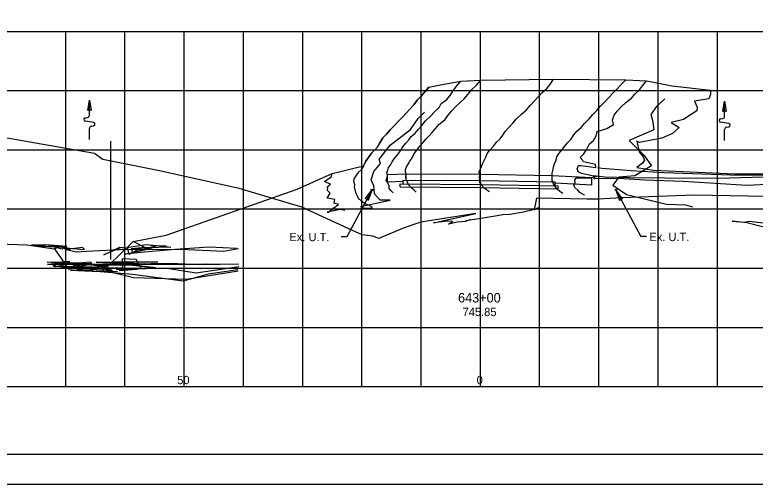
# Model space of a CAD drawing. Extents: x -46 to 154, y -27 to 78.
# Drawn here: x 104.44 to 116.94, y 55.68 to 63.61 of the extents above; entities that cross this region are included whole.
import ezdxf

# ---------------------------------------------------------------- set-up
doc = ezdxf.new("R2010")
doc.units = 0
for name, color, linetype in [('BD_X_Building', 7, 'Continuous'), ('DT_P_Contour_Minor', 7, 'Continuous'), ('DT_X_Break_Line', 7, 'Continuous'), ('DT_X_Contour_Major', 7, 'Continuous'), ('DT_X_Island', 7, 'Continuous'), ('DT_X_Spot_Elev', 7, 'Continuous'), ('DT_X_Void', 7, 'Continuous'), ('GE_P_Alignment_100_Stations', 7, 'Continuous'), ('HY_X_Water_Edge', 7, 'Continuous'), ('PF_X_Ground_Line', 7, 'Continuous'), ('PV_X_COP', 7, 'Continuous'), ('PV_X_Driveway', 7, 'Continuous'), ('PV_X_EOP', 7, 'Continuous'), ('SV_X_Break_Lines', 7, 'Continuous'), ('SV_X_Terrain_Boundary', 7, 'Continuous'), ('SV_X_Toe_of_Slope', 7, 'Continuous'), ('XS_P_Finished_Grade', 7, 'Continuous'), ('XS_P_Pavt_Layers', 7, 'Continuous'), ('XS_P_Text_Info', 7, 'Continuous'), ('XS_X_Pavt', 7, 'Continuous')]:
    doc.layers.add(name, color=color, linetype=linetype)

msp = doc.modelspace()

# ---------------------------------------------------------------- linework, layer by layer
at = {"layer": 'BD_X_Building'}
for points in [[(114.051, 60.565), (114.057, 60.563), (113.981, 60.606), (113.946, 60.646), (113.895, 60.693), (113.878, 60.736), (113.902, 60.772), (113.898, 60.822), (113.926, 60.853), (114.171, 60.854), (114.24, 60.879), (114.168, 60.893), (114.007, 60.927), (113.955, 60.954), (113.937, 61.008), (113.959, 61.063), (113.995, 61.064), (114.253, 61.031), (114.245, 61.077), (114.042, 61.126), (114.031, 61.149), (113.986, 61.197), (114.047, 61.259), (114.095, 61.324), (114.117, 61.371), (114.146, 61.429), (114.212, 61.484), (114.259, 61.565), (114.272, 61.634), (114.439, 61.689), (114.55, 61.755), (114.532, 61.831), (114.56, 61.913), (114.612, 61.98), (114.681, 62.055), (114.756, 62.129), (114.853, 62.201), (114.914, 62.274), (114.987, 62.343), (115.038, 62.407), (115.107, 62.495)], [(110.828, 60.599), (110.83, 60.6), (110.798, 60.636), (110.76, 60.671), (110.76, 60.721), (110.739, 60.77), (110.709, 60.813), (110.729, 60.862), (110.734, 60.902), (110.725, 60.942), (110.737, 60.984), (110.751, 61.027), (110.783, 61.069), (110.815, 61.123), (110.846, 61.177), (110.902, 61.24), (110.952, 61.308), (110.994, 61.378), (111.045, 61.439), (111.096, 61.498), (111.136, 61.552), (111.2, 61.609), (111.253, 61.669), (111.314, 61.737), (111.378, 61.815), (111.459, 61.894), (111.53, 61.968), (111.606, 62.041), (111.638, 62.108), (111.727, 62.172), (111.79, 62.247), (111.837, 62.32), (111.898, 62.4), (111.971, 62.489)]]:
    msp.add_lwpolyline(points, dxfattribs=at)
at = {"layer": 'DT_P_Contour_Minor'}
for p, q in [((105.673, 61.992), (105.702, 62.165)), ((105.702, 62.165), (105.731, 61.991)), ((105.702, 61.909), (105.702, 62.165)), ((116.394, 61.975), (116.423, 62.148)), ((116.423, 62.148), (116.452, 61.974)), ((116.423, 61.892), (116.423, 62.148)), ((105.632, 61.864), (105.672, 61.872)), ((105.673, 61.992), (105.673, 61.992)), ((105.731, 61.991), (105.731, 61.991)), ((116.394, 61.975), (116.394, 61.975)), ((116.452, 61.974), (116.452, 61.975)), ((105.772, 61.788), (105.633, 61.809)), ((116.353, 61.848), (116.393, 61.855)), ((116.493, 61.771), (116.354, 61.792)), ((105.702, 61.503), (105.702, 61.688)), ((105.733, 61.725), (105.773, 61.732)), ((116.423, 61.486), (116.423, 61.671)), ((116.454, 61.708), (116.494, 61.716)), ((110.469, 60.648), (110.047, 59.858)), ((110.355, 60.499), (110.469, 60.648)), ((110.469, 60.648), (110.409, 60.47)), ((114.703, 60.501), (114.59, 60.65)), ((114.59, 60.65), (114.649, 60.471)), ((114.59, 60.65), (115.011, 59.86)), ((110.355, 60.499), (110.355, 60.499)), ((114.703, 60.501), (114.703, 60.501)), ((110.409, 60.47), (110.409, 60.47)), ((114.649, 60.471), (114.649, 60.471)), ((110.047, 59.858), (109.952, 59.858)), ((115.106, 59.86), (115.011, 59.86))]:
    msp.add_line(p, q, dxfattribs=at)
for centre, radius, start, end in [((105.702, 61.947), 0.0527, 56.178, 122.8588), ((105.665, 61.909), 0.0375, 280.6197, 360), ((116.386, 61.892), 0.0375, 280.6197, 360), ((116.423, 61.931), 0.0527, 56.178, 122.8588), ((105.637, 61.837), 0.0281, 100.6197, 261.4692), ((105.768, 61.76), 0.0281, 280.6197, 81.4692), ((116.358, 61.82), 0.0281, 100.6197, 261.4692), ((116.489, 61.743), 0.0281, 280.6197, 81.4692), ((105.74, 61.688), 0.0375, 100.6197, 180), ((116.461, 61.671), 0.0375, 100.6197, 180), ((110.36, 60.443), 0.0563, 28.2924, 94.9732), ((114.699, 60.445), 0.0563, 85.0268, 151.7076)]:
    msp.add_arc(centre, radius, start, end, dxfattribs=at)
at = {"layer": 'DT_X_Break_Line'}
for p, q in [((98.302, 63.328), (126.302, 63.328)), ((105.302, 57.328), (105.302, 63.328)), ((106.302, 57.328), (106.302, 63.328)), ((107.302, 57.328), (107.302, 63.328)), ((108.302, 57.328), (108.302, 63.328)), ((109.302, 57.328), (109.302, 63.328)), ((110.302, 57.328), (110.302, 63.328)), ((111.302, 57.328), (111.302, 63.328)), ((112.302, 57.328), (112.302, 63.328)), ((113.302, 57.328), (113.302, 63.328)), ((114.302, 57.328), (114.302, 63.328)), ((115.302, 57.328), (115.302, 63.328)), ((116.302, 57.328), (116.302, 63.328)), ((98.302, 62.328), (126.302, 62.328)), ((98.302, 61.328), (126.302, 61.328)), ((98.302, 60.328), (126.302, 60.328)), ((98.302, 59.328), (126.302, 59.328)), ((98.302, 58.328), (126.302, 58.328)), ((98.302, 57.328), (126.302, 57.328))]:
    msp.add_line(p, q, dxfattribs=at)
at = {"layer": 'DT_X_Contour_Major'}
msp.add_lwpolyline([(95.552, 55.678), (129.552, 55.678), (129.552, 77.678), (95.552, 77.678)], close=True, dxfattribs=at)
at = {"layer": 'DT_X_Island'}
for p, q in [((110.732, 60.909), (111.048, 60.921)), ((110.732, 60.788), (110.732, 60.909)), ((111.048, 60.816), (111.048, 60.921)), ((111.048, 60.921), (112.302, 60.913)), ((112.302, 60.913), (113.513, 60.891)), ((113.513, 60.787), (113.513, 60.891)), ((113.513, 60.891), (114.182, 60.858)), ((110.732, 60.788), (110.998, 60.798)), ((110.948, 60.75), (112.301, 60.742)), ((110.948, 60.7), (110.948, 60.75)), ((110.998, 60.817), (112.301, 60.808)), ((110.998, 60.75), (110.998, 60.817)), ((112.3, 60.808), (113.563, 60.786)), ((113.563, 60.719), (113.563, 60.786)), ((113.563, 60.767), (114.182, 60.737)), ((114.182, 60.737), (114.182, 60.858)), ((110.948, 60.7), (112.3, 60.692)), ((112.298, 60.692), (113.613, 60.668)), ((112.299, 60.742), (113.613, 60.718)), ((113.613, 60.668), (113.613, 60.718))]:
    msp.add_line(p, q, dxfattribs=at)
at = {"layer": 'DT_X_Spot_Elev'}
msp.add_lwpolyline([(97.052, 77.178), (129.052, 77.178), (129.052, 56.178), (97.052, 56.178)], close=True, dxfattribs=at)
at = {"layer": 'GE_P_Alignment_100_Stations'}
msp.add_line((106.064, 59.472), (106.064, 61.472), dxfattribs=at)
at = {"layer": 'HY_X_Water_Edge'}
for points in [[(114.304, 61.048), (114.298, 61.041), (114.304, 61.024), (114.282, 61.024), (114.849, 60.978), (115.407, 60.944), (116.526, 60.904), (117.965, 60.9)], [(117.263, 60.872), (116.327, 60.843), (115.414, 60.849), (114.812, 60.851), (114.4, 60.866), (114.203, 60.886), (114.256, 60.873), (114.255, 60.87), (114.211, 60.858), (114.232, 60.844), (114.631, 60.848), (115.076, 60.822), (115.727, 60.797), (116.264, 60.763), (116.799, 60.728), (117.38, 60.756)]]:
    msp.add_lwpolyline(points, dxfattribs=at)
at = {"layer": 'PF_X_Ground_Line'}
for points in [[(108.208, 59.299), (107.708, 59.228), (107.287, 59.106), (106.429, 59.222), (105.818, 59.273), (105.48, 59.286), (105.548, 59.311), (105.584, 59.326), (105.567, 59.316), (105.433, 59.335), (105.63, 59.35), (105.741, 59.349), (105.762, 59.296), (105.714, 59.28), (105.15, 59.358), (105.094, 59.354), (105.424, 59.362), (105.484, 59.366), (105.653, 59.352), (105.694, 59.333), (105.572, 59.336), (105.259, 59.349), (105.132, 59.362), (105.065, 59.402), (105.13, 59.358), (105.301, 59.391), (105.528, 59.397), (105.479, 59.32), (105.346, 59.313)], [(108.225, 59.35), (107.505, 59.245), (107.016, 59.321), (106.302, 59.308), (106.156, 59.313), (106.381, 59.31), (106.408, 59.307), (106.37, 59.308), (106.203, 59.286), (106.499, 59.31), (106.578, 59.325), (106.49, 59.472), (106.257, 59.488), (106.259, 59.302), (106.328, 59.298), (106.243, 59.334), (106.231, 59.325), (105.985, 59.329), (105.871, 59.363), (105.73, 59.384), (105.866, 59.373), (106.054, 59.382), (106.383, 59.384), (106.825, 59.336), (106.396, 59.384), (106.335, 59.434), (106.024, 59.375)]]:
    msp.add_lwpolyline(points, dxfattribs=at)
at = {"layer": 'PV_X_COP'}
msp.add_lwpolyline([(111.43, 62.385), (111.357, 62.299), (111.303, 62.233), (111.232, 62.167), (111.178, 62.089), (111.111, 62.012), (111.049, 61.945), (110.979, 61.873), (110.912, 61.807), (110.849, 61.73), (110.782, 61.671), (110.719, 61.59), (110.653, 61.527), (110.606, 61.444), (110.558, 61.365), (110.518, 61.326), (110.461, 61.269), (110.414, 61.195), (110.368, 61.136), (110.327, 61.058), (110.291, 60.991), (110.236, 60.944), (110.2, 60.889), (110.17, 60.843), (110.162, 60.803), (110.166, 60.78), (110.179, 60.741), (110.173, 60.696), (110.182, 60.649), (110.199, 60.596), (110.223, 60.548), (110.244, 60.501), (110.281, 60.476), (110.322, 60.44), (110.365, 60.413), (110.414, 60.397), (110.461, 60.369), (110.468, 60.34), (110.279, 60.336)], dxfattribs=at)
at = {"layer": 'PV_X_Driveway'}
for points in [[(110.016, 60.302), (109.939, 60.318), (109.715, 60.272), (109.736, 60.275), (109.811, 60.338), (109.907, 60.404), (109.835, 60.427), (109.844, 60.486), (109.717, 60.512), (109.766, 60.596), (109.719, 60.638), (109.729, 60.682), (109.713, 60.7), (109.774, 60.748), (109.703, 60.773), (109.668, 60.792), (109.782, 60.872), (109.797, 60.928)], [(108.185, 59.659), (107.724, 59.681), (107.149, 59.644), (106.629, 59.599), (106.292, 59.565), (106.607, 59.63), (106.815, 59.69), (106.596, 59.65), (106.404, 59.661), (106.643, 59.685), (106.736, 59.676), (106.673, 59.646), (106.428, 59.585), (106.42, 59.656), (106.546, 59.639), (106.549, 59.652), (106.372, 59.561), (106.349, 59.661), (106.238, 59.675), (105.945, 59.554), (106.216, 59.684), (106.295, 59.67), (106.661, 59.728), (106.949, 59.697), (107.078, 59.683), (106.65, 59.671), (106.44, 59.777)], [(108.218, 59.656), (107.97, 59.607), (107.364, 59.639), (106.325, 59.641), (105.65, 59.609), (105.479, 59.599), (105.29, 59.642), (105.325, 59.662), (105.375, 59.635), (105.276, 59.668), (105.357, 59.665), (105.618, 59.645), (105.583, 59.677), (105.404, 59.652), (104.966, 59.723), (104.742, 59.708), (105.105, 59.686), (105.244, 59.656), (105.289, 59.693), (105.32, 59.691), (105.111, 59.713), (104.966, 59.72), (104.877, 59.706), (104.725, 59.719), (104.84, 59.72), (104.979, 59.702), (105.239, 59.68), (105.202, 59.686), (105.112, 59.656)]]:
    msp.add_lwpolyline(points, dxfattribs=at)
at = {"layer": 'PV_X_EOP'}
for points in [[(115.418, 62.188), (115.272, 62.059), (115.178, 61.924), (115.207, 61.826), (115.228, 61.663), (114.813, 61.484), (115.064, 61.232), (115.193, 61.056), (114.909, 60.888), (114.64, 60.865), (114.538, 60.728), (114.77, 60.572), (115.445, 60.411), (115.766, 60.4), (115.88, 60.366)], [(110.278, 60.37), (110.781, 60.475), (110.609, 60.478), (110.512, 60.582), (110.504, 60.719), (110.459, 60.82), (110.504, 60.96), (110.613, 61.095), (110.593, 61.167), (110.624, 61.203), (110.778, 61.406), (111.12, 61.669), (111.249, 61.857), (111.358, 61.961)]]:
    msp.add_lwpolyline(points, dxfattribs=at)
for centre in [(110.469, 60.648), (114.59, 60.65)]:
    msp.add_circle(centre, 0.0125, dxfattribs=at)
at = {"layer": 'SV_X_Break_Lines'}
for points in [[(111.217, 60.614), (111.215, 60.612), (111.177, 60.649), (111.133, 60.687), (111.091, 60.736), (111.071, 60.78), (111.051, 60.825), (111.046, 60.871), (111.05, 60.914), (111.039, 60.955), (111.04, 60.996), (111.054, 61.04), (111.081, 61.083), (111.109, 61.137), (111.149, 61.191), (111.177, 61.253), (111.229, 61.32), (111.279, 61.388), (111.336, 61.45), (111.383, 61.508), (111.436, 61.566), (111.488, 61.621), (111.542, 61.686), (111.601, 61.754), (111.699, 61.831), (111.754, 61.909), (111.819, 61.983), (111.889, 62.057), (111.962, 62.127), (112.026, 62.191), (112.095, 62.266), (112.154, 62.339), (112.234, 62.418), (112.308, 62.506)], [(113.691, 60.591), (113.641, 60.623), (113.598, 60.663), (113.563, 60.708), (113.537, 60.75), (113.519, 60.79), (113.511, 60.835), (113.513, 60.885), (113.511, 60.93), (113.522, 60.976), (113.538, 61.027), (113.55, 61.08), (113.579, 61.15), (113.595, 61.207), (113.632, 61.269), (113.682, 61.333), (113.722, 61.384), (113.771, 61.443), (113.826, 61.503), (113.881, 61.578), (113.929, 61.641), (114.002, 61.704), (114.059, 61.774), (114.137, 61.849), (114.202, 61.924), (114.267, 61.989), (114.33, 62.065), (114.404, 62.14), (114.468, 62.211), (114.535, 62.282), (114.606, 62.351), (114.665, 62.417), (114.756, 62.508)]]:
    msp.add_lwpolyline(points, dxfattribs=at)
at = {"layer": 'SV_X_Terrain_Boundary'}
msp.add_lwpolyline([(108.213, 59.279), (107.341, 59.136), (106.446, 59.166), (105.989, 59.277), (105.813, 59.278), (105.966, 59.273), (106.03, 59.322), (105.899, 59.337), (105.937, 59.289), (106.178, 59.273), (106.119, 59.267), (105.751, 59.272), (105.385, 59.291), (105.928, 59.319), (106.017, 59.328), (105.977, 59.313), (105.879, 59.323), (105.638, 59.343), (105.519, 59.352), (105.416, 59.394), (105.506, 59.352), (105.679, 59.389), (105.998, 59.353), (106.105, 59.27), (105.847, 59.34), (105.606, 59.335)], dxfattribs=at)
at = {"layer": 'SV_X_Toe_of_Slope'}
msp.add_lwpolyline([(112.454, 60.619), (112.445, 60.621), (112.406, 60.653), (112.349, 60.688), (112.332, 60.729), (112.293, 60.777), (112.295, 60.815), (112.286, 60.858), (112.293, 60.904), (112.28, 60.954), (112.304, 61.004), (112.323, 61.045), (112.337, 61.092), (112.364, 61.148), (112.393, 61.203), (112.416, 61.264), (112.461, 61.323), (112.521, 61.391), (112.572, 61.455), (112.636, 61.514), (112.682, 61.575), (112.722, 61.637), (112.786, 61.707), (112.851, 61.778), (112.913, 61.853), (112.996, 61.927), (113.083, 62), (113.146, 62.079), (113.217, 62.153), (113.278, 62.221), (113.344, 62.293), (113.422, 62.365), (113.472, 62.427), (113.538, 62.522)], dxfattribs=at)
at = {"layer": 'XS_P_Finished_Grade'}
for points in [[(108.211, 59.39), (107.688, 59.394), (107.261, 59.384), (106.43, 59.391), (105.798, 59.389), (105.433, 59.373), (105.458, 59.391), (105.554, 59.397), (105.556, 59.392), (105.422, 59.395), (105.59, 59.423), (105.71, 59.433), (105.744, 59.413), (105.689, 59.401), (105.114, 59.4), (104.994, 59.391), (105.377, 59.395), (105.44, 59.395), (105.587, 59.401), (105.643, 59.418), (105.493, 59.414), (105.236, 59.42), (105.061, 59.423), (104.991, 59.429), (105.105, 59.433), (105.28, 59.427), (105.354, 59.435), (105.37, 59.439), (105.258, 59.435)], [(108.219, 59.395), (107.606, 59.385), (107.049, 59.405), (106.425, 59.395), (106.177, 59.397), (106.431, 59.395), (106.457, 59.392), (106.426, 59.396), (106.235, 59.406), (106.521, 59.408), (106.633, 59.403), (106.087, 59.393), (105.839, 59.389), (105.699, 59.397), (106.3, 59.401), (106.4, 59.403), (106.312, 59.416), (106.303, 59.412), (106.013, 59.417), (105.982, 59.412), (105.815, 59.43), (105.898, 59.431), (106.109, 59.435), (106.518, 59.435), (106.859, 59.431), (106.482, 59.43), (106.224, 59.374), (106.163, 59.433)]]:
    msp.add_lwpolyline(points, dxfattribs=at)
at = {"layer": 'XS_P_Pavt_Layers'}
for points in [[(104.163, 59.736), (104.646, 59.721), (105.112, 59.656), (105.346, 59.313), (105.606, 59.335), (106.024, 59.375), (106.44, 59.777), (106.999, 59.885), (109.208, 60.664), (109.797, 60.928), (110.327, 61.058), (110.368, 61.136), (110.414, 61.195), (110.461, 61.269), (110.518, 61.326), (110.558, 61.365), (110.606, 61.444), (110.653, 61.527), (110.719, 61.59), (110.782, 61.671), (110.849, 61.73), (110.912, 61.807), (110.979, 61.873), (111.049, 61.945), (111.111, 62.012), (111.178, 62.089), (111.232, 62.167), (111.303, 62.233), (111.357, 62.299), (111.43, 62.385), (111.682, 62.435), (111.942, 62.482), (111.971, 62.489), (112.308, 62.506), (113.538, 62.522), (114.756, 62.508), (115.107, 62.495), (115.169, 62.48), (115.531, 62.407), (116.187, 62.335), (116.189, 62.263), (116.157, 62.19), (115.916, 62.148), (115.959, 62.049), (115.953, 61.988), (115.732, 61.839), (115.52, 61.791), (115.659, 61.703), (115.545, 61.605), (115.366, 61.523), (114.986, 61.449), (114.943, 61.471), (114.981, 61.294), (115.048, 61.208), (115.072, 61.15), (115.04, 61.1), (114.94, 61.029), (115.224, 60.982), (116.592, 60.919), (118.006, 60.922)], [(117.126, 60.54), (115.911, 60.56), (114.687, 60.517), (114.284, 60.496), (114.104, 60.493), (113.251, 60.509), (113.207, 60.312), (113.296, 60.351), (113.215, 60.319), (113.027, 60.276), (112.8, 60.232), (112.682, 60.229), (112.515, 60.199), (112.347, 60.17), (112.058, 60.126), (112.133, 60.147), (112.048, 60.114), (111.908, 60.106), (111.764, 60.071), (111.833, 60.116), (111.755, 60.12), (111.513, 60.095), (112.225, 60.249), (111.294, 60.105), (111.013, 60.009), (110.704, 59.878), (110.59, 59.829), (110.484, 59.868), (110.307, 59.892), (110.143, 59.963), (109.289, 60.359), (108.228, 60.671), (106.857, 60.98), (105.928, 61.161), (105.787, 61.262), (103.469, 61.67)], [(117.787, 59.838), (116.798, 60.092), (116.553, 60.122), (116.758, 60.105), (116.837, 60.121), (117.325, 60.066)]]:
    msp.add_lwpolyline(points, dxfattribs=at)
at = {"layer": 'XS_P_Text_Info'}
msp.add_line((106.996, 59.699), (106.737, 59.707), dxfattribs=at)

# ---------------------------------------------------------------- texts
at = {"layer": 'DT_P_Contour_Minor'}
for p in [(109.078, 59.784), (115.154, 59.785)]:
    msp.add_text('Ex. U.T.', height=0.14, dxfattribs=at).set_placement(p)
at = {"layer": 'DT_X_Void'}
for s, height, p in [('643+00', 0.16, (111.925, 58.748)), ('745.85', 0.14, (112.001, 58.518)), ('50', 0.14, (107.184, 57.368)), ('0', 0.14, (112.239, 57.368))]:
    msp.add_text(s, height=height, dxfattribs=at).set_placement(p)
at = {"layer": 'XS_X_Pavt'}
msp.add_text('744.898', height=0.00432, dxfattribs=at).set_placement((114.77, 60.818))

doc.saveas('drawing.dxf')
